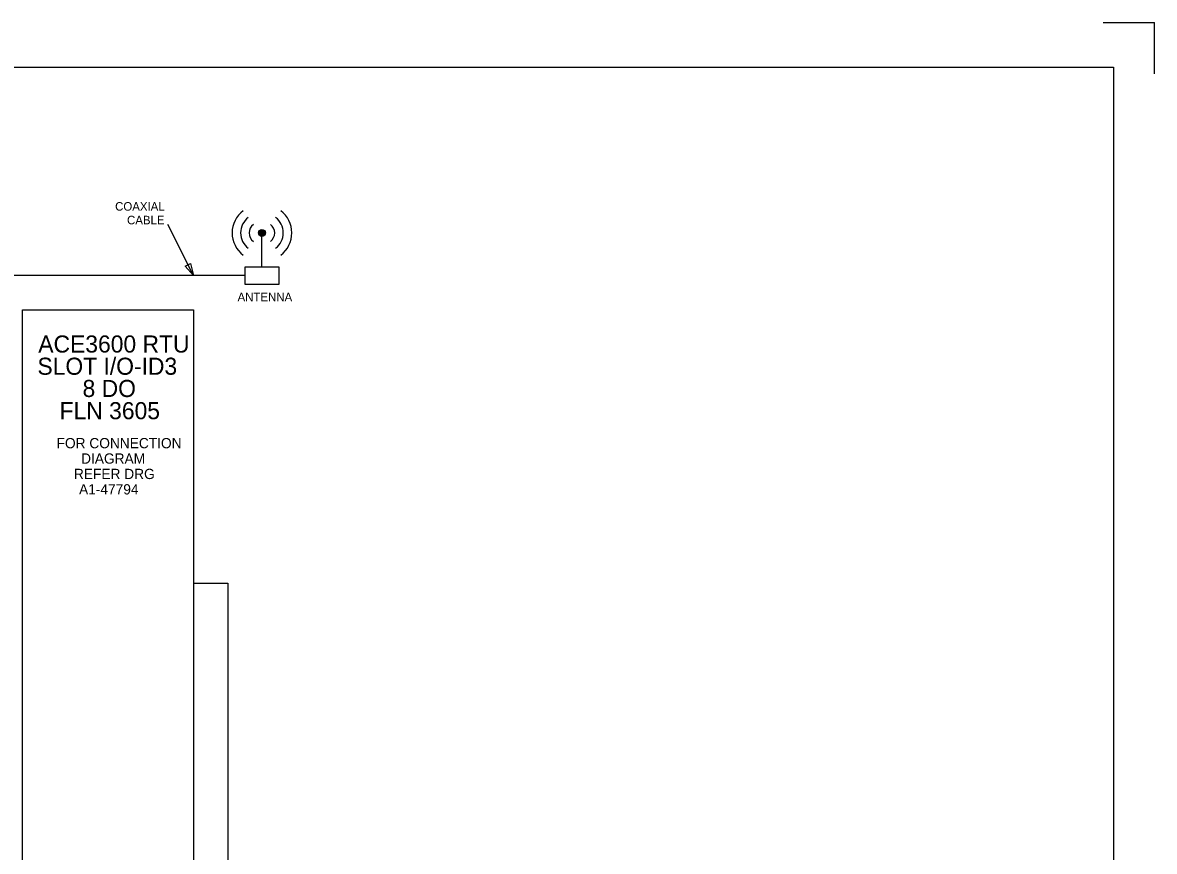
# Model space of a CAD drawing. Extents: x 0 to 841, y 0 to 594.
# Drawn here: x 510 to 841, y 351.6 to 594 of the extents above; entities that cross this region are included whole.
import ezdxf

# ---------------------------------------------------------------- set-up
doc = ezdxf.new("R2010")
doc.units = 0
for name, color, linetype in [('A1BORDER', 7, 'Continuous'), ('Level 1', 7, 'Continuous'), ('Level 10', 7, 'Continuous')]:
    doc.layers.add(name, color=color, linetype=linetype)

msp = doc.modelspace()

# ---------------------------------------------------------------- linework, layer by layer
at = {"layer": 'A1BORDER'}
for p, q in [((826, 594), (841, 594)), ((841, 579), (841, 594)), ((28, 581), (829, 581)), ((829, 581), (829, 15))]:
    msp.add_line(p, q, dxfattribs=at)
at = {"layer": 'Level 1'}
for p, q in [((559.94, 520), (552.47, 535)), ((580, 522.5), (580, 532.5)), ((575, 520), (430, 520)), ((560, 430), (570, 430)), ((570, 430), (570, 210))]:
    msp.add_line(p, q, dxfattribs=at)
for points in [[(559.13, 523.53), (559.94, 520.01), (557.57, 522.73)], [(575, 517.5), (585, 517.5), (585, 522.5), (575, 522.5)], [(510, 510), (560, 510), (560, 160), (510, 160)]]:
    msp.add_lwpolyline(points, close=True, dxfattribs=at)
for centre, radius, start, end in [((579.38, 532.5), 8.12, 126.8699, 233.1301), ((579.38, 532.5), 5.62, 126.8699, 233.1301), ((580.62, 532.5), 5.62, 306.8699, 53.1301), ((580.62, 532.5), 8.12, 306.8699, 53.1301), ((579.38, 532.5), 3.12, 126.8699, 233.1301), ((580.62, 532.5), 3.12, 306.8699, 53.1301)]:
    msp.add_arc(centre, radius, start, end, dxfattribs=at)
at = {"layer": 'Level 10'}
for p, q in [((579.29, 533.2), (580.71, 533.2)), ((580, 533.5), (580, 533.5)), ((579.01, 532.6), (580.99, 532.6)), ((579.02, 532.3), (580.98, 532.3)), ((579.08, 532.9), (580.92, 532.9)), ((579.13, 532), (580.87, 532)), ((579.4, 531.7), (580.6, 531.7))]:
    msp.add_line(p, q, dxfattribs=at)
msp.add_circle((580, 532.5), 1, dxfattribs=at)

# ---------------------------------------------------------------- texts
at = {"layer": 'Level 1'}
for s, height, p in [('COAXIAL', 2.5, (537.05, 539)), ('CABLE', 2.5, (540.54, 535)), ('ANTENNA', 2.5, (572.86, 512.5)), ('ACE3600 RTU', 5, (514.58, 497.5)), ('SLOT I/O-ID3', 5, (514.33, 491)), ('8 DO', 5, (527.53, 484.5)), ('FLN 3605', 5, (520.81, 478)), ('FOR CONNECTION', 3, (519.93, 469.5)), ('DIAGRAM', 3, (527.1, 465)), ('REFER DRG', 3, (525.01, 460.5)), ('A1-47794', 3, (526.5, 456))]:
    msp.add_text(s, height=height, dxfattribs=at).set_placement(p)

doc.saveas('drawing.dxf')
